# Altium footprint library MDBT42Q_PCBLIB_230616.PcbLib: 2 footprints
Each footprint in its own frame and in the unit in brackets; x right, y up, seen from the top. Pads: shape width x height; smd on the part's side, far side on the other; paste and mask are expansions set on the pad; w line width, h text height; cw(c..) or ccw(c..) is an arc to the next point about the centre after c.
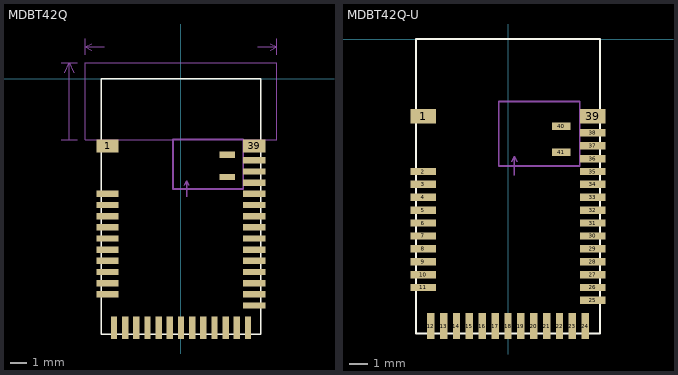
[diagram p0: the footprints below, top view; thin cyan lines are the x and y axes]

## MDBT42Q [mm]
pads (41):
  rect 1.4x0.8 smd mask+0: 1(-4.6,-4.2) 39(4.6,-4.2)
  rect 1.4x0.4 smd mask+0: 2(-4.6,-7.2) 3(-4.6,-7.9) 4(-4.6,-8.6) 5(-4.6,-9.3) 6(-4.6,-10) 7(-4.6,-10.7) 8(-4.6,-11.4) 9(-4.6,-12.1) 10(-4.6,-12.8) 11(-4.6,-13.5) 25(4.6,-14.2) 26(4.6,-13.5) 27(4.6,-12.8) 28(4.6,-12.1) 29(4.6,-11.4) 30(4.6,-10.7) 31(4.6,-10) 32(4.6,-9.3) 33(4.6,-8.6) 34(4.6,-7.9) 35(4.6,-7.2) 36(4.6,-6.5) 37(4.6,-5.8) 38(4.6,-5.1)
  rect 0.4x1.4 smd mask+0: 12(-4.2,-15.6) 13(-3.5,-15.6) 14(-2.8,-15.6) 15(-2.1,-15.6) 16(-1.4,-15.6) 17(-0.7,-15.6) 18(0,-15.6) 19(0.7,-15.6) 20(1.4,-15.6) 21(2.1,-15.6) 22(2.8,-15.6) 23(3.5,-15.6) 24(4.2,-15.6)
  rect 1x0.4 smd mask+0: 40(2.9,-4.75) 41(2.9,-6.15)
TopOverlay:
  lines w0.1: -5,-16 -5,0 0,0 5,0 5,-16 -5,-16
Mechanical2:
  lines w0.05: -7.5,-3.8 -6.5,-3.8 ; -7.5,1 -6.5,1 ; -7.28,0.39 -7,1 ; -7,-3.8 -7,1 ; -6.72,0.39 -7,1 ; -6,1.5 -6,2.5 ; -5.6,1.8 -6,2 ; -5.6,2.2 -6,2 ; -4.8,2 -6,2 ; 4.8,2 6,2 ; 5.6,1.8 6,2 ; 5.6,2.2 6,2 ; 6,0 6,-3.8 ; 6,1.5 6,2.5 ; 6,-3.8 -6,-3.8 -6,1 6,1 6,-3.8
  text "No ground pad" at -2.615,-1.89 h0.45
  text "as wide as possible" at -7.878,-6.096 h0.45
  text "as wide as possible" at -4.075,1.825 h0.45
Mechanical3:
  lines w0.08: 0.2,-6.675 0.35,-6.375 ; 0.35,-7.4 0.35,-6.375 ; 0.5,-6.675 0.35,-6.375
  lines w0.1: -0.5,-6.9 3.9,-6.9 3.9,-3.8 -0.5,-3.8 -0.5,-6.9
  text "Toplayer no ground pad" at -2.8,-7.775 h0.3

## MDBT42Q-U [mm]
pads (41):
  rect 1.4x0.8 smd mask+0: 1(-4.6,-4.2) 39(4.6,-4.2)
  rect 1.4x0.4 smd mask+0: 2(-4.6,-7.2) 3(-4.6,-7.9) 4(-4.6,-8.6) 5(-4.6,-9.3) 6(-4.6,-10) 7(-4.6,-10.7) 8(-4.6,-11.4) 9(-4.6,-12.1) 10(-4.6,-12.8) 11(-4.6,-13.5) 25(4.6,-14.2) 26(4.6,-13.5) 27(4.6,-12.8) 28(4.6,-12.1) 29(4.6,-11.4) 30(4.6,-10.7) 31(4.6,-10) 32(4.6,-9.3) 33(4.6,-8.6) 34(4.6,-7.9) 35(4.6,-7.2) 36(4.6,-6.5) 37(4.6,-5.8) 38(4.6,-5.1)
  rect 0.4x1.4 smd mask+0: 12(-4.2,-15.6) 13(-3.5,-15.6) 14(-2.8,-15.6) 15(-2.1,-15.6) 16(-1.4,-15.6) 17(-0.7,-15.6) 18(0,-15.6) 19(0.7,-15.6) 20(1.4,-15.6) 21(2.1,-15.6) 22(2.8,-15.6) 23(3.5,-15.6) 24(4.2,-15.6)
  rect 1x0.4 smd mask+0: 40(2.9,-4.75) 41(2.9,-6.15)
TopOverlay:
  lines w0.1: -5,-16 5,-16 5,0 0,0 -5,0 -5,-16
Mechanical3:
  lines w0.08: 0.2,-6.675 0.35,-6.375 ; 0.35,-7.4 0.35,-6.375 ; 0.5,-6.675 0.35,-6.375
  lines w0.1: -0.5,-6.9 -0.5,-3.4 3.9,-3.4 3.9,-6.9 -0.5,-6.9
  text "Toplayer no ground pad" at -2.8,-7.775 h0.3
